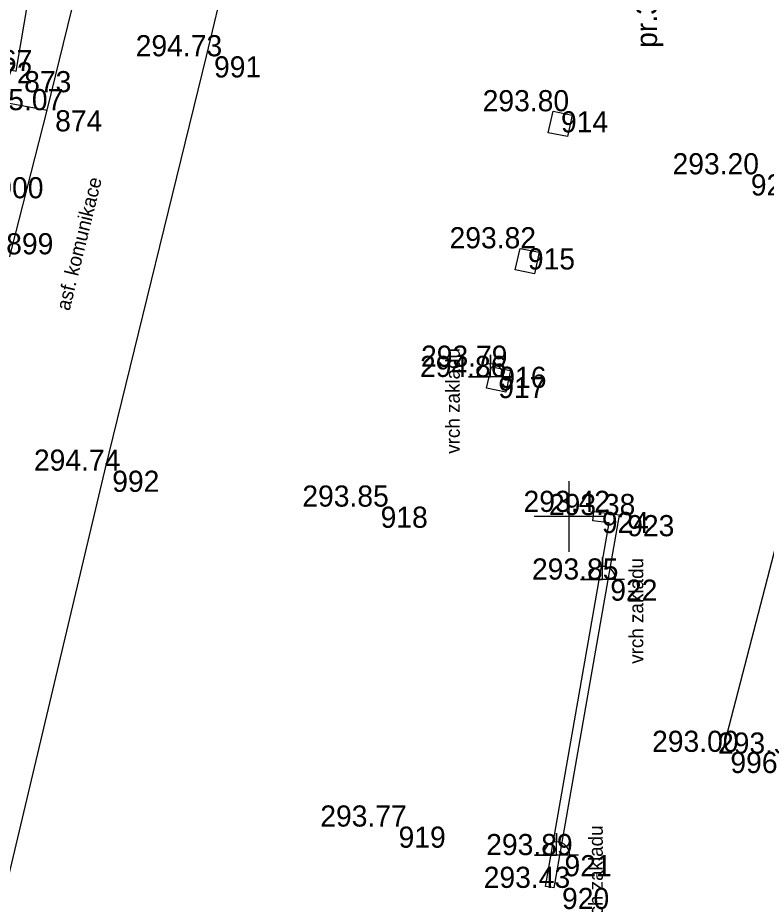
# Model space of a CAD drawing. Extents: x -599970 to -599524, y -1154772 to -1154457.
# Drawn here: x -599765.66 to -599744.41, y -1154661 to -1154635.85 of the extents above; entities that cross this region are included whole.
import ezdxf

# ---------------------------------------------------------------- set-up
doc = ezdxf.new("R2010")
doc.units = 0
for name, color, linetype in [('Z-KRIZKY CTVERCOVE SITE', 7, 'Continuous'), ('Z-PLOT DRATENY', 7, 'Continuous'), ('Z-PODROBNE BODY', 7, 'Continuous'), ('Z-PODROBNE BODY-CISLO', 7, 'Continuous'), ('Z-PODROBNE BODY-VYSKA', 7, 'Continuous'), ('Z-POPISY OBJEKTU A ZPEVNENYCH PLOCH', 7, 'Continuous'), ('Z-PRUMERY KMENU STROMU', 7, 'Continuous'), ('Z-TERENNI HRANY PATY', 7, 'Continuous'), ('Z-VYSKOVE BODY', 7, 'Continuous'), ('Z-ZPEVNENE PLOCHY', 7, 'Continuous')]:
    doc.layers.add(name, color=color, linetype=linetype)

msp = doc.modelspace()

# ---------------------------------------------------------------- linework, layer by layer
at = {"layer": 'Z-KRIZKY CTVERCOVE SITE'}
for p, q in [((-599750, -1154651), (-599750, -1154649)), ((-599749, -1154650), (-599751, -1154650))]:
    msp.add_line(p, q, dxfattribs=at)
at = {"layer": 'Z-PLOT DRATENY'}
msp.add_lwpolyline([(-599745.65, -1154656.68), (-599742.21, -1154643.42), (-599738.73, -1154627.21)], dxfattribs=at)
at = {"layer": 'Z-PODROBNE BODY'}
for p, q in [((-599760.31, -1154636.94), (-599760.31, -1154636.94)), ((-599764.82, -1154638.47), (-599764.82, -1154638.47)), ((-599750.46, -1154638.5), (-599750.46, -1154638.5)), ((-599745.07, -1154640.29), (-599745.07, -1154640.29)), ((-599751.4, -1154642.39), (-599751.4, -1154642.39)), ((-599752.21, -1154645.75), (-599752.21, -1154645.75)), ((-599752.24, -1154646.04), (-599752.24, -1154646.04)), ((-599763.2, -1154648.7), (-599763.2, -1154648.7)), ((-599755.58, -1154649.72), (-599755.58, -1154649.72)), ((-599749.3, -1154649.87), (-599749.3, -1154649.87)), ((-599748.58, -1154649.96), (-599748.58, -1154649.96)), ((-599749.06, -1154651.79), (-599749.06, -1154651.79)), ((-599745.65, -1154656.68), (-599745.65, -1154656.68)), ((-599755.07, -1154658.8), (-599755.07, -1154658.8)), ((-599750.36, -1154659.61), (-599750.36, -1154659.61)), ((-599750.43, -1154660.54), (-599750.43, -1154660.54))]:
    msp.add_line(p, q, dxfattribs=at)
at = {"layer": 'Z-TERENNI HRANY PATY'}
for points in [[(-599759.17, -1154619.3), (-599759.72, -1154618.39), (-599761.8, -1154615.49), (-599764.21, -1154615.82), (-599766.37, -1154617.44), (-599767.34, -1154617.74), (-599772.76, -1154620.37), (-599773.78, -1154623.48), (-599771.1, -1154626.66), (-599770.56, -1154628.5), (-599767.6, -1154637.96), (-599764.82, -1154638.47)], [(-599760.06, -1154619.3), (-599760.06, -1154618.64), (-599762.33, -1154616.65), (-599765, -1154617.66), (-599767.23, -1154619.14), (-599772.56, -1154623.16), (-599769.35, -1154628.39), (-599766.8, -1154637.11), (-599765.7, -1154637.36), (-599764.13, -1154628.13), (-599766.55, -1154621.48), (-599760.06, -1154619.3)]]:
    msp.add_lwpolyline(points, dxfattribs=at)
at = {"layer": 'Z-VYSKOVE BODY'}
for p, q in [((-599752.24, -1154645.415), (-599752.24, -1154645.665)), ((-599752.24, -1154645.665), (-599752.24, -1154645.415)), ((-599752.24, -1154646.04), (-599752.24, -1154645.415)), ((-599752.24, -1154645.415), (-599752.24, -1154645.665)), ((-599751.615, -1154646.04), (-599752.865, -1154646.04)), ((-599752.865, -1154646.04), (-599752.24, -1154646.04)), ((-599751.615, -1154646.04), (-599752.24, -1154646.04)), ((-599749.06, -1154651.165), (-599749.06, -1154651.415)), ((-599749.06, -1154651.415), (-599749.06, -1154651.165)), ((-599749.06, -1154651.79), (-599749.06, -1154651.165)), ((-599749.06, -1154651.165), (-599749.06, -1154651.415)), ((-599748.435, -1154651.79), (-599749.685, -1154651.79)), ((-599749.685, -1154651.79), (-599749.06, -1154651.79)), ((-599748.435, -1154651.79), (-599749.06, -1154651.79)), ((-599750.36, -1154658.985), (-599750.36, -1154659.235)), ((-599750.36, -1154659.235), (-599750.36, -1154658.985)), ((-599750.36, -1154659.61), (-599750.36, -1154658.985)), ((-599750.36, -1154658.985), (-599750.36, -1154659.235)), ((-599749.735, -1154659.61), (-599750.985, -1154659.61)), ((-599750.985, -1154659.61), (-599750.36, -1154659.61)), ((-599749.735, -1154659.61), (-599750.36, -1154659.61))]:
    msp.add_line(p, q, dxfattribs=at)
for centre, start, end in [((-599752.24, -1154646.04), 90, 180), ((-599752.24, -1154646.04), 0, 90), ((-599749.06, -1154651.79), 90, 180), ((-599749.06, -1154651.79), 0, 90), ((-599750.36, -1154659.61), 90, 180), ((-599750.36, -1154659.61), 0, 90)]:
    msp.add_arc(centre, 0.375, start, end, dxfattribs=at)
at = {"layer": 'Z-ZPEVNENE PLOCHY'}
for points in [[(-599754.14, -1154621.91), (-599757.46, -1154625.05), (-599757.52, -1154625.29), (-599760.31, -1154636.94), (-599763.2, -1154648.7), (-599766.8, -1154663.87), (-599769.11, -1154662.8), (-599767.23, -1154647.84), (-599764.82, -1154638.47), (-599762.25, -1154627.96), (-599761.65, -1154625.43)], [(-599749.92, -1154638.61), (-599750.05, -1154639.22), (-599750.6, -1154639.11), (-599750.46, -1154638.5), (-599749.92, -1154638.61)], [(-599750.86, -1154642.5), (-599750.99, -1154643.11), (-599751.54, -1154643), (-599751.4, -1154642.39), (-599750.86, -1154642.5)], [(-599751.67, -1154645.86), (-599751.8, -1154646.47), (-599752.35, -1154646.36), (-599752.21, -1154645.75), (-599751.67, -1154645.86)], [(-599750.43, -1154660.54), (-599750.68, -1154660.5), (-599748.87, -1154650.18), (-599749.33, -1154650.12), (-599749.3, -1154649.87)], [(-599750.43, -1154660.54), (-599748.58, -1154649.96), (-599749.3, -1154649.87)]]:
    msp.add_lwpolyline(points, dxfattribs=at)

# ---------------------------------------------------------------- texts
at = {"layer": 'Z-PODROBNE BODY-CISLO'}
for s, p in [(' 872', (-599766.8, -1154637.71)), (' 991', (-599760.31, -1154637.54)), (' 873', (-599765.7, -1154637.96)), (' 874', (-599764.82, -1154639.07)), (' 914', (-599750.46, -1154639.1)), (' 900', (-599766.49, -1154640.97)), (' 925', (-599745.07, -1154640.89)), (' 899', (-599766.21, -1154642.56)), (' 915', (-599751.4, -1154642.99)), (' 916', (-599752.21, -1154646.35)), (' 917', (-599752.24, -1154646.64)), (' 992', (-599763.2, -1154649.3)), (' 918', (-599755.58, -1154650.32)), (' 924', (-599749.3, -1154650.47)), (' 923', (-599748.58, -1154650.56)), (' 922', (-599749.06, -1154652.39)), (' 996', (-599745.65, -1154657.28)), (' 919', (-599755.07, -1154659.4)), (' 921', (-599750.36, -1154660.21)), (' 920', (-599750.43, -1154661.14))]:
    msp.add_text(s, height=0.6, dxfattribs=at).set_placement(p)
at = {"layer": 'Z-PODROBNE BODY-VYSKA'}
for s, p in [('294.73 ', (-599762.31, -1154636.94)), ('295.67 ', (-599767.7, -1154637.36)), ('295.07 ', (-599766.82, -1154638.47)), ('293.80 ', (-599752.46, -1154638.5)), ('293.20 ', (-599747.07, -1154640.29)), ('293.82 ', (-599753.4, -1154642.39)), ('293.79 ', (-599754.21, -1154645.75)), ('294.86 ', (-599754.24, -1154646.04)), ('294.74 ', (-599765.2, -1154648.7)), ('293.85 ', (-599757.58, -1154649.72)), ('293.42 ', (-599751.3, -1154649.87)), ('293.38 ', (-599750.58, -1154649.96)), ('293.85 ', (-599751.06, -1154651.79)), ('293.00 ', (-599747.65, -1154656.68)), ('293.04 ', (-599745.78, -1154656.73)), ('293.77 ', (-599757.07, -1154658.8)), ('293.89 ', (-599752.36, -1154659.61)), ('293.43 ', (-599752.43, -1154660.54))]:
    msp.add_text(s, height=0.6, dxfattribs=at).set_placement(p)
at = {"layer": 'Z-POPISY OBJEKTU A ZPEVNENYCH PLOCH'}
msp.add_text('asf. komunikace', height=0.4, rotation=76.1933, dxfattribs=at).set_placement((-599764.19, -1154644.18))
at = {"layer": 'Z-PRUMERY KMENU STROMU'}
msp.add_text('pr.30cm', height=0.6, rotation=90, dxfattribs=at).set_placement((-599747.51, -1154636.7))
at = {"layer": 'Z-VYSKOVE BODY'}
for p in [(-599753.11, -1154648.22), (-599747.9, -1154654.18), (-599749.05, -1154661.77)]:
    msp.add_text('vrch zakladu', height=0.4, rotation=90, dxfattribs=at).set_placement(p)

doc.saveas('drawing.dxf')
